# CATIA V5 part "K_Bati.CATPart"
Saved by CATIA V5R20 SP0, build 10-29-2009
Part number: Bati
Bounding box of the stored display mesh (mm): x -290 to 20, y -5 to 0, z -219.996 to 219.996
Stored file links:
  G:\Khaled_CFAO_2011\ST2M\ST2M_GR2\jcoetard\Khaled\CAD_CATIA\K_Bati.CATPart
  J:\Thinkmotion\Thinkmotion_COETARD\Maquette_catia\Maquette_catia_R20_Licence_education\jcharlescoetard.CATPRODUCT\Assemblage_Pince_Prehension_Mors_Paralleles.CATProduct
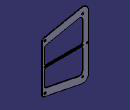
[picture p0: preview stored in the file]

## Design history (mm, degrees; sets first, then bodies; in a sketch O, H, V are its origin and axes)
Set1
  Plane1 "Plan_Ref": linked copy from another document
  Point1 to Point4: linked copy from another document
Body1 (main body)
  Sketch1 on Plane1, origin (0, 0, 0), H (-1, 0, 0), V (0, 0, 1)
    point P1 (-20, 0)
    point P2 (290, 0)
    line L1 (290, 0) -> (290, 180)
    line L2 (242.0947, 219.211) -> (-3.9527, 169.6055)
    line L3 (-20, 150) -> (-20, 0)
    arc A1 centre (250, 180) radius 40 from (290, 180) to (242.0947, 219.211) ccw
    point P3 (290, 180)
    point P4 (242.0947, 219.211)
    point P5 (250, 180)
    arc A2 centre (0, 150) radius 20 from (-3.9527, 169.6055) to (-20, 150) ccw
    point P6 (-3.9527, 169.6055)
    point P7 (-20, 150)
    point P8 (0, 150)
    reference projected point E1 (250, 180) from Point1
    reference projected point E2 (0, 150) from Point2
    point P9 (290, -180)
    point P10 (290, 0)
    line L4 (290, 0) -> (290, -180)
    point P11 (242.0947, -219.211)
    point P12 (250, -180)
    arc A3 centre (250, -180) radius 40 from (290, -180) to (242.0947, -219.211) cw
    point P13 (-3.9527, -169.6055)
    line L5 (242.0947, -219.211) -> (-3.9527, -169.6055)
    point P14 (-20, 0)
    point P15 (-20, -150)
    line L6 (-20, -150) -> (-20, 0)
    point P16 (0, -150)
    arc A4 centre (0, -150) radius 20 from (-3.9527, -169.6055) to (-20, -150) cw
    construction line L7 (0, 0) -> (250, 0)
    point P17 (0, 0)
    point P18 (250, 0)
    line L8 (0, 3) -> (250, 3)
    line L9 (250, -3) -> (0, -3)
    arc A5 centre (250, 0) radius 3 from (250, 3) to (250, -3) cw
    arc A6 centre (0, 0) radius 3 from (0, -3) to (0, 3) cw
    circle A7 centre (280, 0) radius 4
    point P23 (280, 0)
    construction line L10 (250, 450.859) -> (250, 95.5097)
    reference projected point E4 (250, 180) from Point1
    axis line L11 (0, 122.6905) -> (0, -95.5224)
    reference projected point E5 (0, 150) from Point2
    line L12 (8.0237, 121.014) -> (226.0473, 164.9697)
    line L13 (250, 145.3642) -> (250, 18)
    line L14 (240, 8) -> (10, 8)
    line L15 (0, 18) -> (0, 111.2113)
    arc A8 centre (230, 145.3642) radius 20 from (226.0473, 164.9697) to (250, 145.3642) cw
    point P28 (226.0473, 164.9697)
    point P29 (250, 145.3642)
    arc A9 centre (10, 111.2113) radius 10 from (0, 111.2113) to (8.0237, 121.014) cw
    point P31 (0, 111.2113)
    point P32 (8.0237, 121.014)
    arc A10 centre (240, 18) radius 10 from (250, 18) to (240, 8) cw
    point P34 (250, 18)
    point P35 (240, 8)
    arc A11 centre (10, 18) radius 10 from (10, 8) to (0, 18) cw
    point P37 (10, 8)
    point P38 (0, 18)
    point P40 (226.0473, -164.9697)
    point P41 (8.0237, -121.014)
    line L16 (8.0237, -121.014) -> (226.0473, -164.9697)
    point P42 (250, -145.3642)
    arc A12 centre (230, -145.3642) radius 20 from (226.0473, -164.9697) to (250, -145.3642) ccw
    point P44 (250, -18)
    line L17 (250, -145.3642) -> (250, -18)
    point P45 (10, -8)
    point P46 (240, -8)
    line L18 (240, -8) -> (10, -8)
    arc A13 centre (240, -18) radius 10 from (250, -18) to (240, -8) ccw
    point P48 (0, -111.2113)
    arc A14 centre (10, -111.2113) radius 10 from (0, -111.2113) to (8.0237, -121.014) ccw
    point P50 (0, -18)
    arc A15 centre (10, -18) radius 10 from (10, -8) to (0, -18) ccw
    line L19 (0, -18) -> (0, -111.2113)
    circle A16 centre (250, 180) radius 5
    point P52 (250, 180)
    reference projected point E6 (250, 180) from Point1
    circle A17 centre (0, 150) radius 5
    point P53 (0, 150)
    reference projected point E7 (0, 150) from Point2
    circle A18 centre (250, -180) radius 5
    circle A19 centre (0, -150) radius 5
    radius A1 = 40
    radius A2 = 20
    distance L7 L8 = 3
    distance P2 P23 = 10
    distance L12 L2 = 50
    distance L14 L8 = 5
    radius A8 = 20
    radius A9 = 10
    radius A10 = 10
    radius A11 = 10
    coincidence: P1 H, P5 E1, P8 E2, P1 P14, P2 P10, P17 H, P23 H, L10 E4, L10 P12, P18 L10, L11 E5, P16 L11, L11 P17, L13 L10, L15 L11, P52 E6, P53 E7
    vertical: L1 V, L3 V, L10 V, L13 V, L15 V
    tangency: A1 L1, A1 L2, A2 L2, A2 L3, A5 L8, A6 L8, A5 L9, A6 L9, A8 L12, A8 L13, A9 L15, A9 L12, A10 L13, A10 L14, A11 L14, A11 L15
    symmetry: P3 P9 H, P2 P10 H, L1 L4 H, P4 P11 H, A1 A3 H, P6 P13 H, L2 L5 H, P1 P14 H, P7 P15 H, L3 L6 H, A2 A4 H, P28 P40 H, P32 P41 H, L12 L16 H, P29 P42 H, A8 A12 H, P34 P44 H, L13 L17 H, P37 P45 H, P35 P46 H, L14 L18 H, A10 A13 H, P31 P48 H, A9 A14 H, P38 P50 H, A11 A15 H, L15 L19 H, A16 A18 H, A17 A19 H
    horizontal: L7 H, L14 H
  Pad1: profile Sketch1, direction (0, -1, 0), length 5
  Fillet1: radius 2, on start face of Pad1; end face of Pad1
